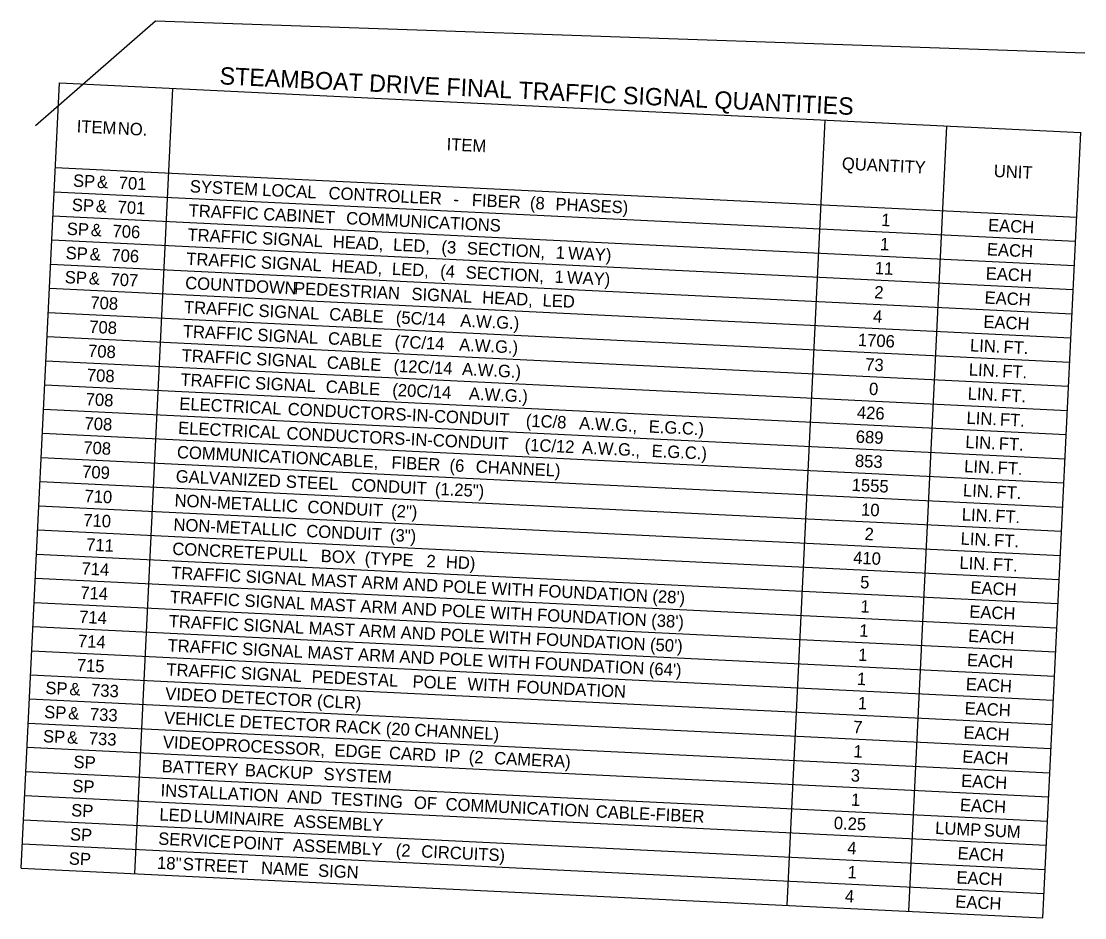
# Model space of a CAD drawing. Extents: x 661030 to 662601, y 642184 to 643065.
# Drawn here: x 661159.7 to 661367.4, y 642606.6 to 642781.6 of the extents above; entities that cross this region are included whole.
import ezdxf

# ---------------------------------------------------------------- set-up
doc = ezdxf.new("R2010")
doc.units = 0
doc.layers.add('R_Dimension', color=7, linetype='Continuous')
doc.layers.add('R_Proposed Road Annot', color=7, linetype='Continuous')

msp = doc.modelspace()

# ---------------------------------------------------------------- linework, layer by layer
at = {"layer": 'R_Dimension'}
for p, q in [((661159.7, 642616.27), (661167.14, 642769.57)), ((661167.14, 642769.57), (661366.64, 642759.88)), ((661181.87, 642615.19), (661189.31, 642768.49)), ((661309.27, 642609), (661316.71, 642762.31)), ((661333.02, 642607.85), (661340.46, 642761.15)), ((661359.19, 642606.58), (661366.64, 642759.88)), ((661166.34, 642753.06), (661365.84, 642743.37)), ((661166.11, 642748.34), (661365.61, 642738.66)), ((661165.88, 642743.63), (661365.38, 642733.94)), ((661165.65, 642738.91), (661365.15, 642729.22)), ((661165.42, 642734.19), (661364.92, 642724.5)), ((661165.19, 642729.47), (661364.69, 642719.79)), ((661164.97, 642724.76), (661364.46, 642715.07)), ((661164.74, 642720.04), (661364.23, 642710.35)), ((661164.51, 642715.32), (661364.01, 642705.64)), ((661164.28, 642710.61), (661363.78, 642700.92)), ((661164.05, 642705.89), (661363.55, 642696.2)), ((661163.82, 642701.17), (661363.32, 642691.48)), ((661163.82, 642701.17), (661363.32, 642691.48)), ((661163.59, 642696.46), (661363.09, 642686.77)), ((661163.36, 642691.74), (661362.86, 642682.05)), ((661163.13, 642687.02), (661362.63, 642677.33)), ((661162.9, 642682.3), (661362.4, 642672.62)), ((661162.68, 642677.59), (661362.17, 642667.9)), ((661162.45, 642672.87), (661361.94, 642663.18)), ((661162.22, 642668.15), (661361.71, 642658.47)), ((661161.99, 642663.44), (661361.49, 642653.75)), ((661161.76, 642658.72), (661361.26, 642649.03)), ((661161.53, 642654), (661361.03, 642644.31)), ((661161.3, 642649.29), (661360.8, 642639.6)), ((661161.07, 642644.57), (661360.57, 642634.88)), ((661160.84, 642639.85), (661360.34, 642630.16)), ((661160.61, 642635.13), (661360.11, 642625.45)), ((661160.38, 642630.42), (661359.88, 642620.73)), ((661160.16, 642625.7), (661359.65, 642616.01)), ((661159.93, 642620.98), (661359.42, 642611.3)), ((661159.7, 642616.27), (661359.19, 642606.58))]:
    msp.add_line(p, q, dxfattribs=at)
at = {"layer": 'R_Proposed Road Annot'}
msp.add_line((661185.94, 642781.61), (661162.47, 642761.19), dxfattribs=at)
msp.add_lwpolyline([(661367.39, 642775.4), (661185.94, 642781.61)], dxfattribs=at)

# ---------------------------------------------------------------- texts
at = {"layer": 'R_Dimension'}
for s, height, p in [('STEAMBOAT DRIVE FINAL TRAFFIC SIGNAL QUANTITIES', 3.3906, (661198.38, 642769.31)), ('ITEM', 2.422, (661170.48, 642759.92)), (' NO.', 2.422, (661177.61, 642759.57)), ('ITEM', 2.422, (661242.72, 642756.41)), ('QUANTITY', 2.422, (661319.92, 642752.66)), ('UNIT', 2.422, (661349.59, 642751.22)), ('SP', 2.422, (661169.76, 642749.32)), (' &', 2.422, (661173.55, 642749.13)), (' 701', 2.422, (661177.79, 642748.93)), ('SYSTEM', 2.422, (661192.58, 642748.21)), (' LOCAL', 2.422, (661205.8, 642747.57)), (' CONTROLLER', 2.4218, (661218.77, 642746.94)), ('SP', 2.422, (661169.53, 642744.6)), (' &', 2.422, (661173.32, 642744.42)), (' 701', 2.422, (661177.57, 642744.21)), (' -', 2.422, (661243.15, 642745.75)), (' FIBER', 2.422, (661246.75, 642745.58)), (' (8', 2.422, (661258.1, 642745.03)), (' PHASES)', 2.422, (661263.08, 642744.79)), ('TRAFFIC', 2.422, (661192.35, 642743.49)), (' CABINET', 2.422, (661206.01, 642742.83)), (' COMMUNICATIONS', 2.4218, (661222.2, 642742.04)), ('SP', 2.422, (661168.55, 642739.92)), ('1', 2.42, (661327.61, 642741.65)), ('EACH', 2.422, (661348.48, 642740.64)), (' &', 2.422, (661172.34, 642739.74)), (' 706', 2.422, (661176.58, 642739.53)), ('TRAFFIC', 2.422, (661192.12, 642738.77)), (' SIGNAL', 2.422, (661205.78, 642738.11)), (' HEAD,', 2.422, (661219.59, 642737.44)), (' LED,', 2.422, (661231.38, 642736.87)), (' (3', 2.422, (661240.81, 642736.41)), (' SECTION,', 2.422, (661245.78, 642736.17)), ('1', 2.42, (661327.38, 642736.93)), ('EACH', 2.422, (661348.25, 642735.92)), ('SP', 2.422, (661168.32, 642735.2)), (' &', 2.422, (661172.11, 642735.02)), (' 706', 2.422, (661176.36, 642734.81)), ('TRAFFIC', 2.422, (661191.89, 642734.06)), (' 1', 2.422, (661263.13, 642735.33)), (' WAY)', 2.422, (661265.55, 642735.21)), (' SIGNAL', 2.422, (661205.55, 642733.39)), (' HEAD,', 2.422, (661219.36, 642732.72)), (' LED,', 2.422, (661231.15, 642732.15)), (' (4', 2.422, (661240.58, 642731.69)), (' SECTION,', 2.422, (661245.55, 642731.45)), ('11', 2.422, (661326.35, 642732.26)), ('SP', 2.422, (661168.15, 642730.48)), (' &', 2.422, (661171.95, 642730.3)), (' 707', 2.422, (661176.19, 642730.09)), ('COUNTDOWN', 2.422, (661191.67, 642729.34)), (' 1', 2.422, (661262.9, 642730.61)), (' WAY)', 2.422, (661265.32, 642730.49)), ('EACH', 2.422, (661348.02, 642731.2)), (' PEDESTRIAN', 2.4218, (661212.03, 642728.35)), ('2', 2.42, (661326.24, 642727.53)), ('708', 2.422, (661173.15, 642725.51)), (' SIGNAL', 2.422, (661234.96, 642727.24)), (' HEAD,', 2.422, (661248.77, 642726.57)), (' LED', 2.422, (661260.56, 642726)), ('EACH', 2.422, (661347.79, 642726.49)), ('TRAFFIC', 2.422, (661191.44, 642724.62)), (' SIGNAL', 2.422, (661205.09, 642723.96)), (' CABLE', 2.422, (661218.9, 642723.29)), (' (5C/14', 2.422, (661231.91, 642722.66)), (' A.W.G.)', 2.422, (661244.5, 642722.05)), ('4', 2.42, (661326.01, 642722.82)), ('EACH', 2.422, (661347.56, 642721.77)), ('708', 2.422, (661172.93, 642720.79)), ('TRAFFIC', 2.422, (661191.21, 642719.91)), (' SIGNAL', 2.422, (661204.86, 642719.24)), (' CABLE', 2.422, (661218.67, 642718.57)), (' (7C/14', 2.422, (661231.68, 642717.94)), (' A.W.G.)', 2.422, (661244.27, 642717.33)), ('1706', 2.422, (661323.05, 642718.23)), ('LIN.', 2.422, (661344.94, 642717.17)), (' FT.', 2.422, (661350.58, 642716.9)), ('708', 2.422, (661172.7, 642716.08)), ('TRAFFIC', 2.422, (661190.98, 642715.19)), (' SIGNAL', 2.422, (661204.64, 642714.53)), (' CABLE', 2.422, (661218.44, 642713.86)), (' (12C/14', 2.422, (661231.45, 642713.22)), ('73', 2.422, (661324.47, 642713.44)), ('708', 2.422, (661172.47, 642711.36)), (' A.W.G.)', 2.422, (661244.84, 642712.57)), ('LIN.', 2.422, (661344.71, 642712.45)), (' FT.', 2.422, (661350.35, 642712.18)), ('TRAFFIC', 2.422, (661190.75, 642710.47)), (' SIGNAL', 2.422, (661204.41, 642709.81)), (' CABLE', 2.422, (661218.22, 642709.14)), (' (20C/14', 2.422, (661231.22, 642708.51)), ('0', 2.42, (661325.22, 642708.67)), ('708', 2.422, (661172.24, 642706.64)), (' A.W.G.)', 2.422, (661246.18, 642707.78)), ('LIN.', 2.422, (661344.49, 642707.74)), (' FT.', 2.422, (661350.12, 642707.46)), ('ELECTRICAL', 2.422, (661190.52, 642705.76)), (' CONDUCTORS-IN-CONDUIT', 2.4218, (661210.79, 642704.77)), (' (1C/8', 2.422, (661257.3, 642702.51)), ('426', 2.422, (661322.86, 642704.06)), ('LIN.', 2.422, (661344.26, 642703.02)), (' FT.', 2.422, (661349.89, 642702.74)), ('708', 2.422, (661172.01, 642701.93)), ('ELECTRICAL', 2.422, (661190.29, 642701.04)), (' A.W.G.,', 2.422, (661267.72, 642702.01)), (' E.G.C.)', 2.422, (661281.3, 642701.35)), (' CONDUCTORS-IN-CONDUIT', 2.4218, (661210.56, 642700.05)), ('689', 2.422, (661322.63, 642699.34)), ('LIN.', 2.422, (661344.03, 642698.3)), ('708', 2.422, (661171.78, 642697.21)), ('COMMUNICATION', 2.4218, (661190.06, 642696.32)), (' (1C/12', 2.422, (661257.07, 642697.8)), (' A.W.G.,', 2.422, (661268.29, 642697.25)), (' E.G.C.)', 2.422, (661281.87, 642696.59)), (' FT.', 2.422, (661349.67, 642698.03)), (' CABLE,', 2.422, (661216.98, 642695.01)), (' FIBER', 2.422, (661231.05, 642694.33)), ('853', 2.422, (661322.47, 642694.62)), ('709', 2.422, (661171.54, 642692.49)), (' (6', 2.422, (661242.4, 642693.78)), (' CHANNEL)', 2.422, (661247.51, 642693.53)), ('LIN.', 2.422, (661343.8, 642693.58)), (' FT.', 2.422, (661349.44, 642693.31)), ('GALVANIZED', 2.422, (661189.83, 642691.6)), (' STEEL', 2.422, (661210.42, 642690.6)), (' CONDUIT', 2.422, (661223.2, 642689.98)), ('1555', 2.422, (661321.84, 642689.92)), (' (1.25")', 2.422, (661239.55, 642689.19)), ('LIN.', 2.422, (661343.57, 642688.87)), (' FT.', 2.422, (661349.21, 642688.59)), ('710', 2.422, (661172, 642687.74)), ('NON-METALLIC', 2.4218, (661189.6, 642686.89)), (' CONDUIT', 2.422, (661214.65, 642685.67)), (' (2")', 2.422, (661230.99, 642684.88)), ('10', 2.422, (661323.67, 642685.11)), ('LIN.', 2.422, (661343.34, 642684.15)), (' FT.', 2.422, (661348.98, 642683.88)), ('710', 2.422, (661171.77, 642683.03)), ('NON-METALLIC', 2.4218, (661189.38, 642682.17)), (' CONDUIT', 2.422, (661214.42, 642680.95)), (' (3")', 2.422, (661230.76, 642680.16)), ('2', 2.42, (661324.35, 642680.34)), ('711', 2.422, (661172.33, 642678.27)), ('CONCRETE', 2.422, (661189.15, 642677.45)), ('LIN.', 2.422, (661343.11, 642679.43)), (' FT.', 2.422, (661348.75, 642679.16)), (' PULL', 2.422, (661206.67, 642676.6)), (' BOX', 2.422, (661217.24, 642676.09)), (' (TYPE', 2.422, (661225.83, 642675.67)), ('410', 2.422, (661322.13, 642675.72)), ('714', 2.422, (661171.42, 642673.59)), (' 2', 2.422, (661237.89, 642675.09)), (' HD)', 2.422, (661241.68, 642674.9)), ('LIN.', 2.422, (661342.88, 642674.72)), (' FT.', 2.422, (661348.52, 642674.44)), ("TRAFFIC SIGNAL MAST ARM AND POLE WITH FOUNDATION (28')", 2.4218, (661188.92, 642672.74)), ('5', 2.42, (661323.49, 642670.93)), ('EACH', 2.422, (661345.04, 642669.88)), ('714', 2.422, (661171.19, 642668.87)), ("TRAFFIC SIGNAL MAST ARM AND POLE WITH FOUNDATION (38')", 2.4218, (661188.69, 642668.02)), ('1', 2.42, (661323.55, 642666.2)), ('EACH', 2.422, (661344.81, 642665.17)), ('714', 2.422, (661170.96, 642664.15)), ("TRAFFIC SIGNAL MAST ARM AND POLE WITH FOUNDATION (50')", 2.4218, (661188.46, 642663.3)), ('1', 2.42, (661323.32, 642661.48)), ('714', 2.422, (661170.73, 642659.44)), ('EACH', 2.422, (661344.59, 642660.45)), ("TRAFFIC SIGNAL MAST ARM AND POLE WITH FOUNDATION (64')", 2.4218, (661188.23, 642658.59)), ('1', 2.42, (661323.09, 642656.76)), ('715', 2.422, (661170.5, 642654.72)), ('EACH', 2.422, (661344.36, 642655.73)), ('TRAFFIC', 2.422, (661188, 642653.87)), (' SIGNAL', 2.422, (661201.66, 642653.21)), (' PEDESTAL', 2.422, (661215.47, 642652.53)), (' POLE', 2.422, (661235.18, 642651.58)), (' WITH', 2.422, (661245.9, 642651.06)), (' FOUNDATION', 2.4218, (661255.45, 642650.59)), ('1', 2.42, (661322.86, 642652.05)), ('EACH', 2.422, (661344.13, 642651.02)), ('SP', 2.422, (661164.36, 642650.29)), (' &', 2.422, (661168.15, 642650.1)), (' 733', 2.422, (661172.39, 642649.9)), ('VIDEO DETECTOR (CLR)', 2.4218, (661187.77, 642649.15)), ('1', 2.42, (661323.03, 642647.31)), ('EACH', 2.422, (661343.9, 642646.3)), ('SP', 2.422, (661164.13, 642645.57)), (' &', 2.422, (661167.92, 642645.39)), (' 733', 2.422, (661172.16, 642645.18)), ('VEHICLE DETECTOR RACK (20 CHANNEL)', 2.4218, (661187.54, 642644.43)), ('7', 2.42, (661322.12, 642642.63)), ('SP', 2.422, (661163.9, 642640.85)), (' &', 2.422, (661167.69, 642640.67)), (' 733', 2.422, (661171.94, 642640.46)), ('EACH', 2.422, (661343.67, 642641.58)), ('VIDEO', 2.422, (661187.31, 642639.72)), (' PROCESSOR,', 2.4218, (661196.51, 642639.27)), (' EDGE', 2.422, (661219.92, 642638.13)), ('SP', 2.422, (661169.86, 642635.84)), (' CARD', 2.422, (661230.57, 642637.62)), (' IP', 2.422, (661241.43, 642637.09)), (' (2', 2.422, (661246.15, 642636.86)), (' CAMERA)', 2.422, (661251.12, 642636.62)), ('1', 2.42, (661322.17, 642637.9)), ('EACH', 2.422, (661343.44, 642636.86)), ('BATTERY', 2.422, (661187.08, 642635)), (' BACKUP', 2.422, (661202.44, 642634.25)), (' SYSTEM', 2.422, (661217.79, 642633.51)), ('3', 2.42, (661321.66, 642633.19)), ('EACH', 2.422, (661343.21, 642632.15)), ('SP', 2.422, (661169.63, 642631.12)), ('INSTALLATION', 2.4218, (661186.86, 642630.28)), (' AND', 2.422, (661210.68, 642629.13)), (' TESTING', 2.422, (661219.25, 642628.71)), (' OF', 2.422, (661235.44, 642627.92)), (' COMMUNICATION', 2.4218, (661241.62, 642627.62)), ('1', 2.42, (661321.71, 642628.46)), ('SP', 2.422, (661169.4, 642626.4)), ('LED', 2.422, (661186.63, 642625.57)), (' CABLE-FIBER', 2.4218, (661270.95, 642626.2)), ('EACH', 2.422, (661342.98, 642627.43)), (' LUMINAIRE', 2.422, (661192.47, 642625.28)), (' ASSEMBLY', 2.422, (661212, 642624.33)), ('0.25', 2.422, (661318.34, 642623.9)), ('SP', 2.422, (661169.17, 642621.69)), ('LUMP', 2.422, (661338.14, 642622.94)), (' SUM', 2.422, (661346.73, 642622.52)), ('SERVICE', 2.422, (661186.4, 642620.85)), (' POINT', 2.422, (661200.07, 642620.19)), (' ASSEMBLY', 2.422, (661211.81, 642619.62)), (' (2', 2.422, (661231.9, 642618.64)), (' CIRCUITS)', 2.422, (661236.87, 642618.4)), ('4', 2.42, (661320.97, 642619.04)), ('EACH', 2.422, (661342.52, 642618)), ('SP', 2.422, (661168.94, 642616.97)), ('18"', 2.422, (661186.17, 642616.13)), (' STREET', 2.422, (661190.3, 642615.93)), (' NAME', 2.422, (661205.58, 642615.19)), (' SIGN', 2.422, (661216.72, 642614.65)), ('1', 2.42, (661321.03, 642614.31)), ('EACH', 2.422, (661342.29, 642613.28)), ('4', 2.42, (661320.51, 642609.61)), ('EACH', 2.422, (661342.07, 642608.56))]:
    msp.add_text(s, height=height, rotation=357.2199, dxfattribs=at).set_placement(p)

doc.saveas('drawing.dxf')
